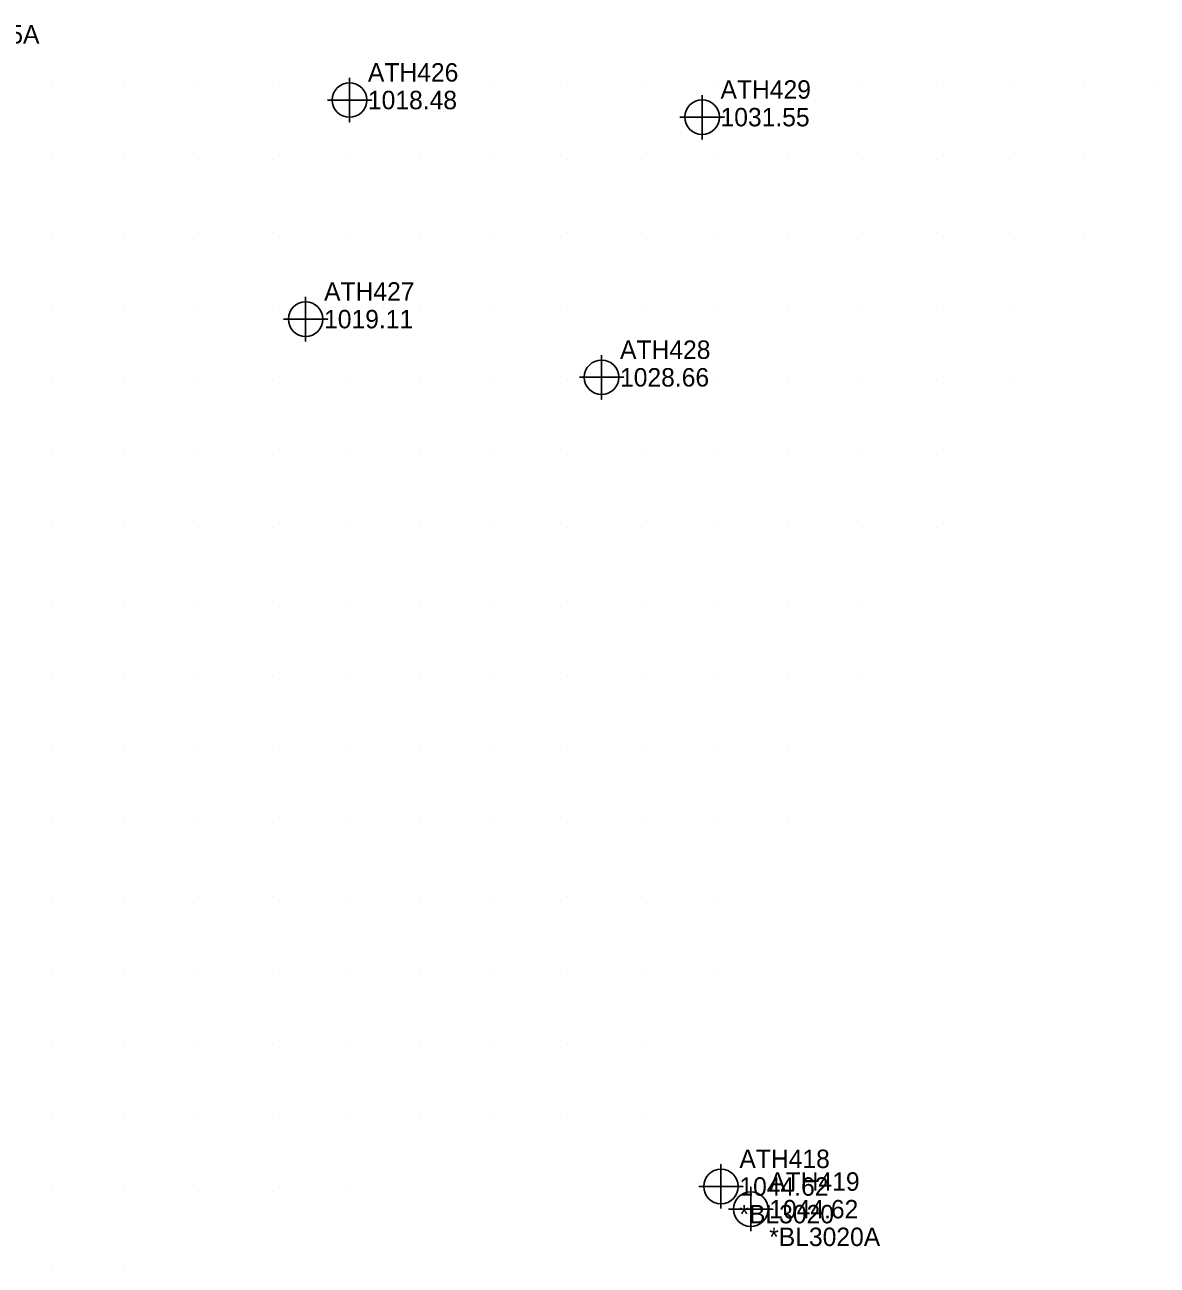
# Model space of a CAD drawing. Extents: x 1116680 to 1117499, y 661040 to 661703.
# Drawn here: x 1117186.4 to 1117340, y 661200 to 661368.2 of the extents above; entities that cross this region are included whole.
import ezdxf

# ---------------------------------------------------------------- set-up
doc = ezdxf.new("R2010")
doc.units = 0
for name, color, linetype in [('Exist DTM Breakline Cogo Comment', 7, 'Continuous'), ('Exist DTM QL2 LIDAR Elevation Point', 7, 'Continuous'), ('Exist DTM Regular Point CELL', 7, 'Continuous'), ('Exist DTM Regular Point Cogo Elevation', 7, 'Continuous'), ('Exist DTM Regular Point Cogo Number', 7, 'Continuous'), ('Exist Railroads Standard Gauge Cogo Comment', 7, 'Continuous'), ('Exist Railroads Standard Gauge Cogo Elevation', 7, 'Continuous'), ('Exist Railroads Standard Gauge Cogo Number', 7, 'Continuous'), ('Exist Railroads Standard Gauge Cogo Point CELL', 7, 'Continuous')]:
    doc.layers.add(name, color=color, linetype=linetype)

msp = doc.modelspace()

# ---------------------------------------------------------------- linework, layer by layer
at = {"layer": 'Exist DTM QL2 LIDAR Elevation Point'}
for p, q in [((1117190, 661360), (1117190, 661360)), ((1117200, 661360), (1117200, 661360)), ((1117210, 661360), (1117210, 661360)), ((1117220, 661360), (1117220, 661360)), ((1117240, 661360), (1117240, 661360)), ((1117250, 661360), (1117250, 661360)), ((1117260, 661360), (1117260, 661360)), ((1117270, 661360), (1117270, 661360)), ((1117280, 661360), (1117280, 661360)), ((1117290, 661360), (1117290, 661360)), ((1117300, 661360), (1117300, 661360)), ((1117310, 661360), (1117310, 661360)), ((1117320, 661360), (1117320, 661360)), ((1117330, 661360), (1117330, 661360)), ((1117340, 661360), (1117340, 661360)), ((1117190, 661350), (1117190, 661350)), ((1117200, 661350), (1117200, 661350)), ((1117210, 661350), (1117210, 661350)), ((1117220, 661350), (1117220, 661350)), ((1117230, 661350), (1117230, 661350)), ((1117240, 661350), (1117240, 661350)), ((1117250, 661350), (1117250, 661350)), ((1117260, 661350), (1117260, 661350)), ((1117270, 661350), (1117270, 661350)), ((1117280, 661350), (1117280, 661350)), ((1117290, 661350), (1117290, 661350)), ((1117300, 661350), (1117300, 661350)), ((1117310, 661350), (1117310, 661350)), ((1117320, 661350), (1117320, 661350)), ((1117330, 661350), (1117330, 661350)), ((1117190, 661340), (1117190, 661340)), ((1117200, 661340), (1117200, 661340)), ((1117210, 661340), (1117210, 661340)), ((1117220, 661340), (1117220, 661340)), ((1117230, 661340), (1117230, 661340)), ((1117240, 661340), (1117240, 661340)), ((1117250, 661340), (1117250, 661340)), ((1117260, 661340), (1117260, 661340)), ((1117270, 661340), (1117270, 661340)), ((1117280, 661340), (1117280, 661340)), ((1117290, 661340), (1117290, 661340)), ((1117300, 661340), (1117300, 661340)), ((1117310, 661340), (1117310, 661340)), ((1117320, 661340), (1117320, 661340)), ((1117330, 661340), (1117330, 661340)), ((1117190, 661330), (1117190, 661330)), ((1117200, 661330), (1117200, 661330)), ((1117210, 661330), (1117210, 661330)), ((1117220, 661330), (1117220, 661330)), ((1117230, 661330), (1117230, 661330)), ((1117240, 661330), (1117240, 661330)), ((1117250, 661330), (1117250, 661330)), ((1117260, 661330), (1117260, 661330)), ((1117270, 661330), (1117270, 661330)), ((1117280, 661330), (1117280, 661330)), ((1117290, 661330), (1117290, 661330)), ((1117300, 661330), (1117300, 661330)), ((1117310, 661330), (1117310, 661330)), ((1117320, 661330), (1117320, 661330)), ((1117190, 661320), (1117190, 661320)), ((1117200, 661320), (1117200, 661320)), ((1117210, 661320), (1117210, 661320)), ((1117220, 661320), (1117220, 661320)), ((1117230, 661320), (1117230, 661320)), ((1117240, 661320), (1117240, 661320)), ((1117250, 661320), (1117250, 661320)), ((1117260, 661320), (1117260, 661320)), ((1117270, 661320), (1117270, 661320)), ((1117280, 661320), (1117280, 661320)), ((1117290, 661320), (1117290, 661320)), ((1117300, 661320), (1117300, 661320)), ((1117310, 661320), (1117310, 661320)), ((1117320, 661320), (1117320, 661320)), ((1117190, 661310), (1117190, 661310)), ((1117200, 661310), (1117200, 661310)), ((1117210, 661310), (1117210, 661310)), ((1117220, 661310), (1117220, 661310)), ((1117230, 661310), (1117230, 661310)), ((1117240, 661310), (1117240, 661310)), ((1117250, 661310), (1117250, 661310)), ((1117260, 661310), (1117260, 661310)), ((1117270, 661310), (1117270, 661310)), ((1117280, 661310), (1117280, 661310)), ((1117290, 661310), (1117290, 661310)), ((1117300, 661310), (1117300, 661310)), ((1117310, 661310), (1117310, 661310)), ((1117190, 661300), (1117190, 661300)), ((1117200, 661300), (1117200, 661300)), ((1117210, 661300), (1117210, 661300)), ((1117220, 661300), (1117220, 661300)), ((1117230, 661300), (1117230, 661300)), ((1117240, 661300), (1117240, 661300)), ((1117250, 661300), (1117250, 661300)), ((1117260, 661300), (1117260, 661300)), ((1117270, 661300), (1117270, 661300)), ((1117280, 661300), (1117280, 661300)), ((1117290, 661300), (1117290, 661300)), ((1117300, 661300), (1117300, 661300)), ((1117310, 661300), (1117310, 661300)), ((1117190, 661290), (1117190, 661290)), ((1117200, 661290), (1117200, 661290)), ((1117210, 661290), (1117210, 661290)), ((1117220, 661290), (1117220, 661290)), ((1117230, 661290), (1117230, 661290)), ((1117240, 661290), (1117240, 661290)), ((1117250, 661290), (1117250, 661290)), ((1117260, 661290), (1117260, 661290)), ((1117270, 661290), (1117270, 661290)), ((1117280, 661290), (1117280, 661290)), ((1117290, 661290), (1117290, 661290)), ((1117300, 661290), (1117300, 661290)), ((1117190, 661280), (1117190, 661280)), ((1117200, 661280), (1117200, 661280)), ((1117210, 661280), (1117210, 661280)), ((1117220, 661280), (1117220, 661280)), ((1117230, 661280), (1117230, 661280)), ((1117240, 661280), (1117240, 661280)), ((1117250, 661280), (1117250, 661280)), ((1117260, 661280), (1117260, 661280)), ((1117270, 661280), (1117270, 661280)), ((1117280, 661280), (1117280, 661280)), ((1117290, 661280), (1117290, 661280)), ((1117300, 661280), (1117300, 661280)), ((1117190, 661270), (1117190, 661270)), ((1117200, 661270), (1117200, 661270)), ((1117210, 661270), (1117210, 661270)), ((1117220, 661270), (1117220, 661270)), ((1117230, 661270), (1117230, 661270)), ((1117240, 661270), (1117240, 661270)), ((1117250, 661270), (1117250, 661270)), ((1117260, 661270), (1117260, 661270)), ((1117270, 661270), (1117270, 661270)), ((1117280, 661270), (1117280, 661270)), ((1117290, 661270), (1117290, 661270)), ((1117190, 661260), (1117190, 661260)), ((1117200, 661260), (1117200, 661260)), ((1117210, 661260), (1117210, 661260)), ((1117220, 661260), (1117220, 661260)), ((1117230, 661260), (1117230, 661260)), ((1117240, 661260), (1117240, 661260)), ((1117250, 661260), (1117250, 661260)), ((1117260, 661260), (1117260, 661260)), ((1117270, 661260), (1117270, 661260)), ((1117280, 661260), (1117280, 661260)), ((1117290, 661260), (1117290, 661260)), ((1117190, 661250), (1117190, 661250)), ((1117200, 661250), (1117200, 661250)), ((1117210, 661250), (1117210, 661250)), ((1117220, 661250), (1117220, 661250)), ((1117230, 661250), (1117230, 661250)), ((1117240, 661250), (1117240, 661250)), ((1117250, 661250), (1117250, 661250)), ((1117260, 661250), (1117260, 661250)), ((1117270, 661250), (1117270, 661250)), ((1117280, 661250), (1117280, 661250)), ((1117190, 661240), (1117190, 661240)), ((1117200, 661240), (1117200, 661240)), ((1117210, 661240), (1117210, 661240)), ((1117220, 661240), (1117220, 661240)), ((1117230, 661240), (1117230, 661240)), ((1117240, 661240), (1117240, 661240)), ((1117250, 661240), (1117250, 661240)), ((1117260, 661240), (1117260, 661240)), ((1117270, 661240), (1117270, 661240)), ((1117280, 661240), (1117280, 661240)), ((1117190, 661230), (1117190, 661230)), ((1117200, 661230), (1117200, 661230)), ((1117210, 661230), (1117210, 661230)), ((1117220, 661230), (1117220, 661230)), ((1117230, 661230), (1117230, 661230)), ((1117240, 661230), (1117240, 661230)), ((1117250, 661230), (1117250, 661230)), ((1117260, 661230), (1117260, 661230)), ((1117270, 661230), (1117270, 661230)), ((1117190, 661220), (1117190, 661220)), ((1117200, 661220), (1117200, 661220)), ((1117210, 661220), (1117210, 661220)), ((1117220, 661220), (1117220, 661220)), ((1117230, 661220), (1117230, 661220)), ((1117240, 661220), (1117240, 661220)), ((1117250, 661220), (1117250, 661220)), ((1117260, 661220), (1117260, 661220)), ((1117270, 661220), (1117270, 661220)), ((1117190, 661210), (1117190, 661210)), ((1117200, 661210), (1117200, 661210)), ((1117210, 661210), (1117210, 661210)), ((1117220, 661210), (1117220, 661210)), ((1117230, 661210), (1117230, 661210)), ((1117190, 661200), (1117190, 661200)), ((1117200, 661200), (1117200, 661200))]:
    msp.add_line(p, q, dxfattribs=at)
at = {"layer": 'Exist DTM Regular Point CELL'}
for points in [[(1117230.452, 661361.024), (1117230.452, 661355.024), (1117230.452, 661358.024), (1117233.452, 661358.024), (1117227.452, 661358.024)], [(1117278.273, 661358.706), (1117278.273, 661352.706), (1117278.273, 661355.706), (1117281.273, 661355.706), (1117275.273, 661355.706)], [(1117224.505, 661331.311), (1117224.505, 661325.311), (1117224.505, 661328.311), (1117227.505, 661328.311), (1117221.505, 661328.311)], [(1117264.643, 661323.416), (1117264.643, 661317.416), (1117264.643, 661320.416), (1117267.643, 661320.416), (1117261.643, 661320.416)]]:
    msp.add_lwpolyline(points, dxfattribs=at)
for centre in [(1117230.452, 661358.024), (1117278.273, 661355.706), (1117224.505, 661328.311), (1117264.643, 661320.416)]:
    msp.add_circle(centre, 2.344, dxfattribs=at)
at = {"layer": 'Exist Railroads Standard Gauge Cogo Point CELL'}
for points in [[(1117277.834, 661210.675), (1117283.834, 661210.675), (1117280.834, 661210.675), (1117280.834, 661213.675), (1117280.834, 661207.675)], [(1117281.877, 661207.597), (1117287.877, 661207.597), (1117284.877, 661207.597), (1117284.877, 661210.597), (1117284.877, 661204.597)]]:
    msp.add_lwpolyline(points, dxfattribs=at)
for centre in [(1117280.834, 661210.675), (1117284.877, 661207.597)]:
    msp.add_circle(centre, 2.344, dxfattribs=at)

# ---------------------------------------------------------------- texts
at = {"layer": 'Exist DTM Breakline Cogo Comment'}
msp.add_text('*BL4005A', height=2.5, dxfattribs=at).set_placement((1117173.343, 661365.689))
at = {"layer": 'Exist DTM Regular Point Cogo Elevation'}
for s, p in [('1018.48', (1117232.952, 661356.774)), ('1031.55', (1117280.773, 661354.456)), ('1019.11', (1117227.005, 661327.061)), ('1028.66', (1117267.143, 661319.166))]:
    msp.add_text(s, height=2.5, dxfattribs=at).set_placement(p)
at = {"layer": 'Exist DTM Regular Point Cogo Number'}
for s, p in [('ATH426', (1117232.952, 661360.524)), ('ATH429', (1117280.773, 661358.206)), ('ATH427', (1117227.005, 661330.811)), ('ATH428', (1117267.143, 661322.916))]:
    msp.add_text(s, height=2.5, dxfattribs=at).set_placement(p)
at = {"layer": 'Exist Railroads Standard Gauge Cogo Comment'}
for s, p in [('*BL3020', (1117283.334, 661205.675)), ('*BL3020A', (1117287.377, 661202.597))]:
    msp.add_text(s, height=2.5, dxfattribs=at).set_placement(p)
at = {"layer": 'Exist Railroads Standard Gauge Cogo Elevation'}
for p in [(1117283.334, 661209.425), (1117287.377, 661206.347)]:
    msp.add_text('1044.62', height=2.5, dxfattribs=at).set_placement(p)
at = {"layer": 'Exist Railroads Standard Gauge Cogo Number'}
for s, p in [('ATH418', (1117283.334, 661213.175)), ('ATH419', (1117287.377, 661210.097))]:
    msp.add_text(s, height=2.5, dxfattribs=at).set_placement(p)

doc.saveas('drawing.dxf')
